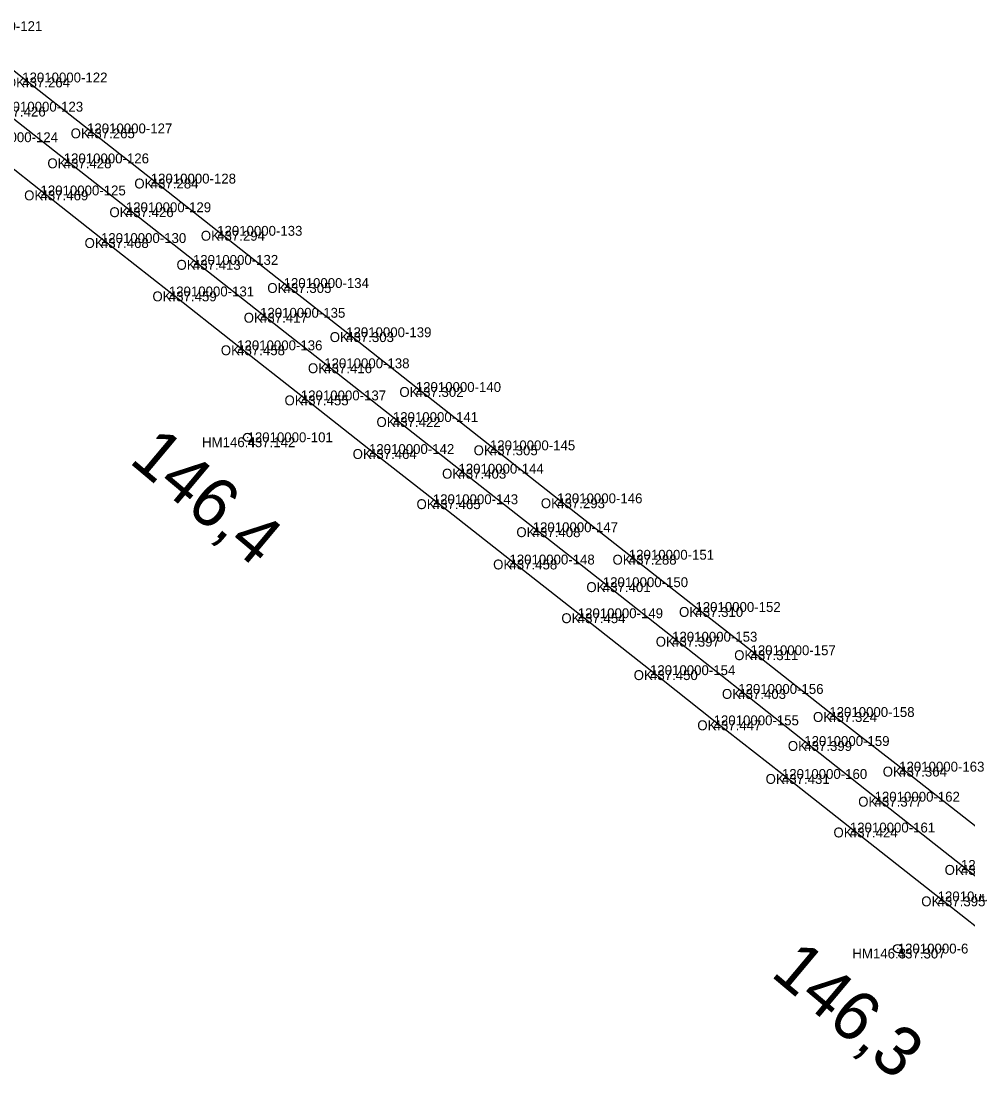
# Model space of a CAD drawing. Extents: x -653665 to -652742, y -1166300 to -1165487.
# Drawn here: x -653141.2 to -653026.3, y -1166017.1 to -1165889.1 of the extents above; entities that cross this region are included whole.
import ezdxf

# ---------------------------------------------------------------- set-up
doc = ezdxf.new("R2010")
doc.units = 0
for name, color, linetype in [('Vrstva 1', 7, 'Continuous'), ('Vrstva 60', 7, 'Continuous'), ('Vrstva 61', 7, 'Continuous'), ('Vrstva 62', 7, 'Continuous'), ('Vrstva 7', 7, 'Continuous')]:
    doc.layers.add(name, color=color, linetype=linetype)

msp = doc.modelspace()

# ---------------------------------------------------------------- linework, layer by layer
at = {"layer": 'Vrstva 1'}
for points in [[(-653024.35, -1165987.67), (-653034.62, -1165979.64), (-653043.1, -1165973.01), (-653052.66, -1165965.51), (-653059.35, -1165960.26), (-653067.43, -1165953.92), (-653076.13, -1165947.07), (-653084.29, -1165940.64), (-653093.29, -1165933.56), (-653101.74, -1165926.91), (-653109.33, -1165920.94), (-653117.4, -1165914.6), (-653125.46, -1165908.26), (-653133.19, -1165902.17), (-653141.06, -1165895.99), (-653148.97, -1165889.76)], [(-653023.89, -1165994.12), (-653027.12, -1165991.57), (-653037.6, -1165983.29), (-653046.14, -1165976.53), (-653054.15, -1165970.21), (-653062.18, -1165963.87), (-653070.59, -1165957.25), (-653079.1, -1165950.58), (-653088.11, -1165943.48), (-653096.07, -1165937.21), (-653104.4, -1165930.68), (-653112.19, -1165924.55), (-653120.34, -1165918.13), (-653128.48, -1165911.74), (-653136.02, -1165905.81), (-653144.01, -1165899.53)], [(-653021.84, -1166001.78), (-653029.95, -1165995.39), (-653040.6, -1165987.03), (-653048.85, -1165980.53), (-653057.14, -1165974.02), (-653064.86, -1165967.93), (-653073.63, -1165961.02), (-653081.92, -1165954.5), (-653091.22, -1165947.18), (-653098.97, -1165941.09), (-653107.24, -1165934.58), (-653114.97, -1165928.5), (-653123.26, -1165921.96), (-653131.5, -1165915.48), (-653138.84, -1165909.7), (-653147.06, -1165903.24)]]:
    msp.add_lwpolyline(points, dxfattribs=at)
at = {"layer": 'Vrstva 60'}
for p, q in [((-653141.06, -1165895.99), (-653141.06, -1165895.99)), ((-653133.19, -1165902.17), (-653133.19, -1165902.17)), ((-653136.02, -1165905.81), (-653136.02, -1165905.81)), ((-653125.46, -1165908.26), (-653125.46, -1165908.26)), ((-653138.84, -1165909.7), (-653138.84, -1165909.7)), ((-653128.48, -1165911.74), (-653128.48, -1165911.74)), ((-653131.5, -1165915.48), (-653131.5, -1165915.48)), ((-653117.4, -1165914.6), (-653117.4, -1165914.6)), ((-653120.34, -1165918.13), (-653120.34, -1165918.13)), ((-653109.33, -1165920.94), (-653109.33, -1165920.94)), ((-653123.26, -1165921.96), (-653123.26, -1165921.96)), ((-653112.19, -1165924.55), (-653112.19, -1165924.55)), ((-653101.74, -1165926.91), (-653101.74, -1165926.91)), ((-653114.97, -1165928.5), (-653114.97, -1165928.5)), ((-653104.4, -1165930.68), (-653104.4, -1165930.68)), ((-653093.29, -1165933.56), (-653093.29, -1165933.56)), ((-653107.24, -1165934.58), (-653107.24, -1165934.58)), ((-653096.07, -1165937.21), (-653096.07, -1165937.21)), ((-653113.71, -1165939.66), (-653113.71, -1165939.66)), ((-653098.97, -1165941.09), (-653098.97, -1165941.09)), ((-653084.29, -1165940.64), (-653084.29, -1165940.64)), ((-653088.11, -1165943.48), (-653088.11, -1165943.48)), ((-653091.22, -1165947.18), (-653091.22, -1165947.18)), ((-653076.13, -1165947.07), (-653076.13, -1165947.07)), ((-653079.1, -1165950.58), (-653079.1, -1165950.58)), ((-653067.43, -1165953.92), (-653067.43, -1165953.92)), ((-653081.92, -1165954.5), (-653081.92, -1165954.5)), ((-653070.59, -1165957.25), (-653070.59, -1165957.25)), ((-653059.35, -1165960.26), (-653059.35, -1165960.26)), ((-653073.63, -1165961.02), (-653073.63, -1165961.02)), ((-653062.18, -1165963.87), (-653062.18, -1165963.87)), ((-653052.66, -1165965.51), (-653052.66, -1165965.51)), ((-653064.86, -1165967.93), (-653064.86, -1165967.93)), ((-653054.15, -1165970.21), (-653054.15, -1165970.21)), ((-653043.1, -1165973.01), (-653043.1, -1165973.01)), ((-653057.14, -1165974.02), (-653057.14, -1165974.02)), ((-653046.14, -1165976.53), (-653046.14, -1165976.53)), ((-653034.62, -1165979.64), (-653034.62, -1165979.64)), ((-653048.85, -1165980.53), (-653048.85, -1165980.53)), ((-653037.6, -1165983.29), (-653037.6, -1165983.29)), ((-653040.6, -1165987.03), (-653040.6, -1165987.03)), ((-653027.12, -1165991.57), (-653027.12, -1165991.57)), ((-653029.95, -1165995.39), (-653029.95, -1165995.39)), ((-653034.79, -1166001.72), (-653034.79, -1166001.72))]:
    msp.add_line(p, q, dxfattribs=at)
at = {"layer": 'Vrstva 7'}
for p, q in [((-653113.75, -1165939.63), (-653113.68, -1165939.69)), ((-653034.83, -1166001.68), (-653034.75, -1166001.75))]:
    msp.add_line(p, q, dxfattribs=at)
for centre in [(-653113.71, -1165939.66), (-653034.79, -1166001.72)]:
    msp.add_circle(centre, 0.5, dxfattribs=at)

# ---------------------------------------------------------------- texts
at = {"layer": 'Vrstva 60'}
for s, p in [('12010000-121', (-653148.97, -1165890.36)), ('12010000-122', (-653141.06, -1165896.59)), ('12010000-123', (-653144.01, -1165900.13)), ('12010000-127', (-653133.19, -1165902.77)), ('12010000-124', (-653147.06, -1165903.84)), ('12010000-126', (-653136.02, -1165906.41)), ('12010000-128', (-653125.46, -1165908.86)), ('12010000-125', (-653138.84, -1165910.3)), ('12010000-129', (-653128.48, -1165912.34)), ('12010000-133', (-653117.4, -1165915.2)), ('12010000-130', (-653131.5, -1165916.08)), ('12010000-132', (-653120.34, -1165918.73)), ('12010000-134', (-653109.33, -1165921.54)), ('12010000-131', (-653123.26, -1165922.56)), ('12010000-135', (-653112.19, -1165925.15)), ('12010000-139', (-653101.74, -1165927.51)), ('12010000-136', (-653114.97, -1165929.1)), ('12010000-138', (-653104.4, -1165931.28)), ('12010000-140', (-653093.29, -1165934.16)), ('12010000-137', (-653107.24, -1165935.18)), ('12010000-141', (-653096.07, -1165937.81)), ('12010000-101', (-653113.71, -1165940.26)), ('12010000-145', (-653084.29, -1165941.24)), ('12010000-142', (-653098.97, -1165941.69)), ('12010000-144', (-653088.11, -1165944.08)), ('12010000-146', (-653076.13, -1165947.67)), ('12010000-143', (-653091.22, -1165947.78)), ('12010000-147', (-653079.1, -1165951.18)), ('12010000-148', (-653081.92, -1165955.1)), ('12010000-151', (-653067.43, -1165954.52)), ('12010000-150', (-653070.59, -1165957.85)), ('12010000-149', (-653073.63, -1165961.62)), ('12010000-152', (-653059.35, -1165960.86)), ('12010000-153', (-653062.18, -1165964.47)), ('12010000-157', (-653052.66, -1165966.11)), ('12010000-154', (-653064.86, -1165968.53)), ('12010000-156', (-653054.15, -1165970.81)), ('12010000-155', (-653057.14, -1165974.62)), ('12010000-158', (-653043.1, -1165973.61)), ('12010000-159', (-653046.14, -1165977.13)), ('12010000-163', (-653034.62, -1165980.24)), ('12010000-160', (-653048.85, -1165981.13)), ('12010000-162', (-653037.6, -1165983.89)), ('12010000-161', (-653040.6, -1165987.63)), ('12010000-49', (-653027.12, -1165992.17)), ('12010000-50', (-653029.95, -1165995.99)), ('12010000-6', (-653034.79, -1166002.32))]:
    msp.add_text(s, height=1.2, dxfattribs=at).set_placement(p)
at = {"layer": 'Vrstva 61'}
for s, p in [('437.264', (-653141.06, -1165897.19)), ('437.426', (-653144.01, -1165900.73)), ('437.265', (-653133.19, -1165903.37)), ('437.428', (-653136.02, -1165907.01)), ('437.284', (-653125.46, -1165909.46)), ('437.469', (-653138.84, -1165910.9)), ('437.426', (-653128.48, -1165912.94)), ('437.468', (-653131.5, -1165916.68)), ('437.294', (-653117.4, -1165915.8)), ('437.413', (-653120.34, -1165919.33)), ('437.305', (-653109.33, -1165922.14)), ('437.459', (-653123.26, -1165923.16)), ('437.417', (-653112.19, -1165925.75)), ('437.303', (-653101.74, -1165928.1)), ('437.458', (-653114.97, -1165929.7)), ('437.416', (-653104.4, -1165931.88)), ('437.302', (-653093.29, -1165934.76)), ('437.455', (-653107.24, -1165935.78)), ('437.422', (-653096.07, -1165938.41)), ('437.142', (-653113.71, -1165940.86)), ('437.464', (-653098.97, -1165942.29)), ('437.305', (-653084.29, -1165941.84)), ('437.403', (-653088.11, -1165944.68)), ('437.465', (-653091.22, -1165948.38)), ('437.293', (-653076.13, -1165948.27)), ('437.408', (-653079.1, -1165951.78)), ('437.288', (-653067.43, -1165955.12)), ('437.458', (-653081.92, -1165955.7)), ('437.401', (-653070.59, -1165958.45)), ('437.310', (-653059.35, -1165961.46)), ('437.454', (-653073.63, -1165962.22)), ('437.397', (-653062.18, -1165965.07)), ('437.311', (-653052.66, -1165966.71)), ('437.450', (-653064.86, -1165969.13)), ('437.403', (-653054.15, -1165971.41)), ('437.324', (-653043.1, -1165974.21)), ('437.447', (-653057.14, -1165975.22)), ('437.399', (-653046.14, -1165977.73)), ('437.364', (-653034.62, -1165980.84)), ('437.431', (-653048.85, -1165981.73)), ('437.377', (-653037.6, -1165984.49)), ('437.424', (-653040.6, -1165988.23)), ('437.368', (-653027.12, -1165992.77)), ('437.395', (-653029.95, -1165996.59)), ('437.307', (-653034.79, -1166002.92))]:
    msp.add_text(s, height=1.2, dxfattribs=at).set_placement(p)
at = {"layer": 'Vrstva 62'}
for s, p in [('OK', (-653143.04, -1165897.19)), ('OK', (-653135.18, -1165903.37)), ('OK', (-653138, -1165907.01)), ('OK', (-653127.45, -1165909.46)), ('OK', (-653140.82, -1165910.9)), ('OK', (-653130.47, -1165912.94)), ('OK', (-653133.49, -1165916.68)), ('OK', (-653119.38, -1165915.8)), ('OK', (-653122.33, -1165919.33)), ('OK', (-653111.31, -1165922.14)), ('OK', (-653125.25, -1165923.16)), ('OK', (-653114.17, -1165925.75)), ('OK', (-653103.73, -1165928.1)), ('OK', (-653116.95, -1165929.7)), ('OK', (-653106.38, -1165931.88)), ('OK', (-653095.28, -1165934.76)), ('OK', (-653109.22, -1165935.78)), ('OK', (-653098.06, -1165938.41)), ('HM146.4', (-653119.23, -1165940.86)), ('OK', (-653100.95, -1165942.29)), ('OK', (-653086.27, -1165941.84)), ('OK', (-653090.1, -1165944.68)), ('OK', (-653093.2, -1165948.38)), ('OK', (-653078.11, -1165948.27)), ('OK', (-653081.08, -1165951.78)), ('OK', (-653069.41, -1165955.12)), ('OK', (-653083.9, -1165955.7)), ('OK', (-653072.58, -1165958.45)), ('OK', (-653061.34, -1165961.46)), ('OK', (-653075.62, -1165962.22)), ('OK', (-653064.16, -1165965.07)), ('OK', (-653054.64, -1165966.71)), ('OK', (-653066.84, -1165969.13)), ('OK', (-653056.13, -1165971.41)), ('OK', (-653045.08, -1165974.21)), ('OK', (-653059.12, -1165975.22)), ('OK', (-653048.13, -1165977.73)), ('OK', (-653036.61, -1165980.84)), ('OK', (-653050.83, -1165981.73)), ('OK', (-653039.59, -1165984.49)), ('OK', (-653042.59, -1165988.23)), ('OK', (-653029.1, -1165992.77)), ('OK', (-653031.94, -1165996.59)), ('HM146.3', (-653040.3, -1166002.92))]:
    msp.add_text(s, height=1.2, dxfattribs=at).set_placement(p)
at = {"layer": 'Vrstva 7'}
for s, p in [('146,4', (-653128.22, -1165942.64)), ('146,3', (-653050.35, -1166004.94))]:
    msp.add_text(s, height=6, rotation=320, dxfattribs=at).set_placement(p)

doc.saveas('drawing.dxf')
